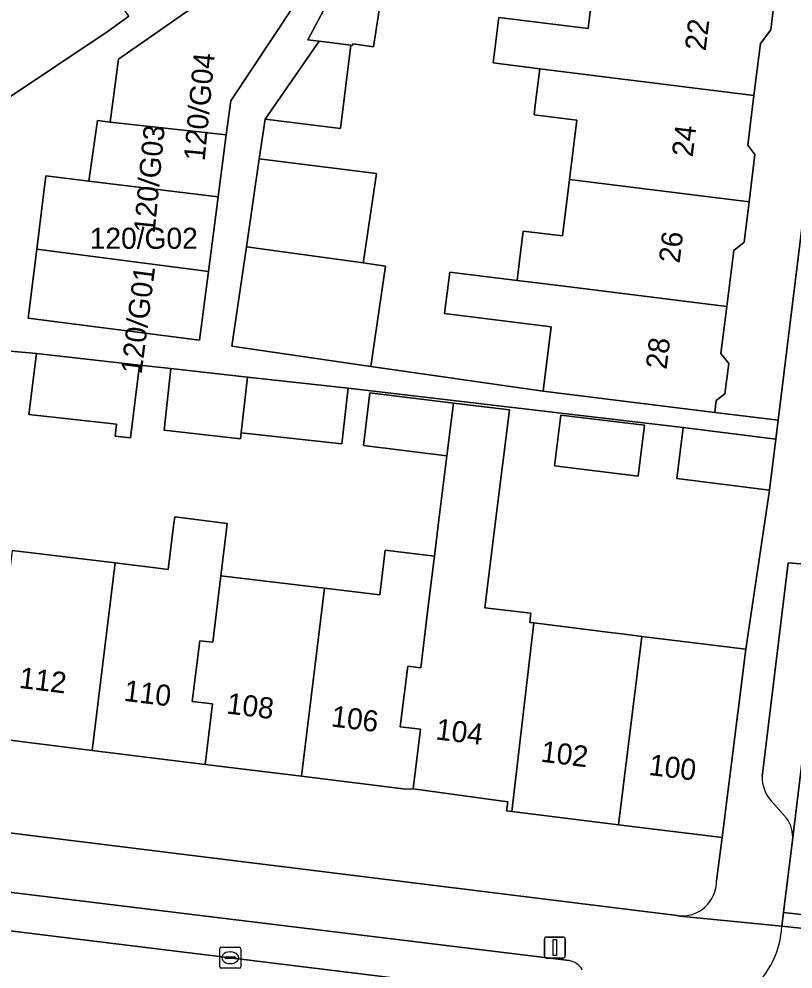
# Model space of a CAD drawing. Extents: x 158086 to 159499, y 382904 to 383981.
# Drawn here: x 158208.93 to 158245.67, y 383286 to 383331.09 of the extents above; entities that cross this region are included whole.
import ezdxf

# ---------------------------------------------------------------- set-up
doc = ezdxf.new("R2010")
doc.units = 0
for name, color, linetype in [('IMGEO_Erf', 7, 'Continuous'), ('IMGEO_Kolk', 7, 'Continuous'), ('IMGEO_Lichtmast', 7, 'Continuous'), ('IMGEO_Muur', 7, 'Continuous'), ('IMGEO_Pand', 7, 'Continuous'), ('IMGEO_Pand_nummerreeks', 7, 'Continuous'), ('IMGEO_Parkeervlak_open', 7, 'Continuous'), ('IMGEO_Rijbaan_lokaal_open', 7, 'Continuous'), ('IMGEO_Voetpad_open', 7, 'Continuous')]:
    doc.layers.add(name, color=color, linetype=linetype)

msp = doc.modelspace()

# ---------------------------------------------------------------- linework, layer by layer
at = {"layer": 'IMGEO_Erf'}
for points in [[(158208.245, 383327.218), (158213.164, 383330.52), (158214.145, 383331.232), (158211.565, 383335.002), (158211.969, 383335.279), (158213.527, 383336.345), (158215.489, 383337.688), (158217.964, 383334.072), (158221.444, 383336.596), (158219.026, 383340.05), (158221.516, 383341.793), (158226.433, 383345.235), (158227.791, 383343.295), (158229.777, 383346.725), (158229.616, 383346.945), (158220.677, 383360.064), (158217.541, 383357.927), (158220.353, 383353.836), (158222.314, 383350.973), (158222.133, 383350.849), (158222.008, 383351.03), (158217.367, 383347.854), (158212.597, 383344.59), (158207.828, 383341.326)], [(158244.848, 383332.474), (158244.614, 383330.581), (158244.127, 383329.936), (158243.821, 383327.463), (158243.529, 383325.098), (158243.866, 383324.666), (158243.587, 383322.411), (158243.351, 383320.497), (158242.857, 383320.112), (158242.527, 383317.443), (158242.251, 383315.216), (158242.62, 383314.743), (158242.442, 383313.3), (158242.029, 383312.978), (158241.96, 383312.42), (158244.969, 383312.049), (158248.754, 383342.754)], [(158226.417, 383334.071), (158225.755, 383329.77), (158224.779, 383329.913), (158224.768, 383329.839), (158224.678, 383329.85), (158224.188, 383325.889), (158220.615, 383326.331), (158220.339, 383324.451), (158225.898, 383323.758), (158225.286, 383319.593), (158225.274, 383319.512), (158226.329, 383319.357), (158225.631, 383314.6), (158233.817, 383313.428), (158234.195, 383316.488), (158229.132, 383317.114), (158229.377, 383319.083), (158232.578, 383318.684), (158232.695, 383319.619), (158232.87, 383321.027), (158234.728, 383320.796), (158235.059, 383323.474), (158235.407, 383326.289), (158233.386, 383326.539), (158233.435, 383327.001), (158233.651, 383328.731), (158231.447, 383329.005), (158231.714, 383331.169), (158235.946, 383330.645), (158236.304, 383333.54)], [(158244.558, 383308.736), (158240.162, 383309.282), (158240.462, 383311.698), (158224.555, 383313.567), (158224.261, 383310.922), (158219.479, 383311.454), (158219.448, 383311.171), (158215.817, 383311.575), (158216.142, 383314.503), (158214.649, 383314.669), (158214.226, 383311.213), (158213.501, 383311.294), (158213.564, 383311.862), (158209.401, 383312.325), (158209.755, 383315.214), (158208.52, 383315.331)], [(158208.611, 383305.869), (158213.499, 383305.277), (158215.542, 383305.029), (158216.018, 383304.971), (158216.272, 383307.044), (158216.323, 383307.459), (158218.819, 383307.154), (158218.768, 383306.738), (158218.515, 383304.669), (158223.441, 383304.072), (158226.063, 383303.755), (158226.32, 383305.874), (158228.647, 383305.592), (158228.86, 383307.328), (158229.239, 383310.366), (158225.285, 383310.845), (158225.588, 383313.346), (158229.551, 383312.866), (158232.209, 383312.542), (158231.519, 383307.003), (158231.048, 383303.151), (158233.231, 383302.886), (158233.176, 383302.449), (158233.37, 383302.425), (158237.125, 383301.959), (158237.544, 383301.907), (158238.492, 383301.789), (158243.427, 383301.176), (158244.558, 383308.736)], [(158242.045, 383290.194), (158242.318, 383292.241), (158237.395, 383292.848), (158232.321, 383293.474), (158232.077, 383293.504), (158232.131, 383293.941), (158227.639, 383294.56), (158227.294, 383294.539), (158222.349, 383295.15), (158217.761, 383295.716), (158212.41, 383296.378), (158207.86, 383296.94)], [(158186.591, 383295.165), (158240.182, 383288.537)]]:
    msp.add_lwpolyline(points, dxfattribs=at)
msp.add_lwpolyline([(158234.354, 383309.878), (158234.649, 383312.293), (158238.617, 383311.808), (158238.321, 383309.393)], close=True, dxfattribs=at)
msp.add_arc((158240.399, 383290.169), 1.647, 262.44, 0.8614, dxfattribs=at)
at = {"layer": 'IMGEO_Kolk'}
for p, q in [((158218.46, 383286.111), (158218.46, 383286.963)), ((158218.535, 383287.037), (158219.387, 383287.037)), ((158218.948, 383286.817), (158218.973, 383286.817)), ((158219.461, 383286.963), (158219.461, 383286.111)), ((158218.719, 383286.531), (158218.719, 383286.543)), ((158219.157, 383286.494), (158218.759, 383286.494)), ((158218.762, 383286.58), (158219.16, 383286.58)), ((158219.203, 383286.543), (158219.203, 383286.531)), ((158219.387, 383286.037), (158218.535, 383286.037)), ((158218.971, 383286.257), (158218.946, 383286.257))]:
    msp.add_line(p, q, dxfattribs=at)
for points in [[(158218.46, 383286.111), (158218.46, 383286.963)], [(158218.535, 383287.037), (158219.387, 383287.037)], [(158219.461, 383286.963), (158219.461, 383286.111)], [(158219.387, 383286.037), (158218.535, 383286.037)]]:
    msp.add_lwpolyline(points, dxfattribs=at)
for centre, radius, start, end in [((158218.537, 383286.961), 0.0765, 91.552, 178.448), ((158218.537, 383286.961), 0.0765, 91.552, 178.448), ((158219.385, 383286.961), 0.0765, 1.552, 88.448), ((158219.385, 383286.961), 0.0765, 1.552, 88.448), ((158218.759, 383286.54), 0.0403, 85.8775, 175.7526), ((158218.756, 383286.53), 0.0366, 178.938, 274.7102), ((158219.16, 383286.537), 0.043, 264.8664, 352.4533), ((158219.164, 383286.542), 0.0386, 1.7309, 96.639), ((158218.537, 383286.113), 0.0765, 181.552, 268.448), ((158218.537, 383286.113), 0.0765, 181.552, 268.448), ((158219.385, 383286.113), 0.0765, 271.552, 358.448), ((158219.385, 383286.113), 0.0765, 271.552, 358.448)]:
    msp.add_arc(centre, radius, start, end, dxfattribs=at)
for centre, major_axis, ratio, start_param, end_param in [((158218.947, 383286.537), (-0.387, 0.002), 0.722429, 4.712389, 7.853982), ((158218.972, 383286.537), (-0.39, 0.002), 0.717154, 1.570796, 4.712389)]:
    msp.add_ellipse(centre, major_axis=major_axis, ratio=ratio, start_param=start_param, end_param=end_param, dxfattribs=at)
at = {"layer": 'IMGEO_Lichtmast'}
for p, q in [((158233.87, 383286.621), (158233.87, 383287.421)), ((158233.87, 383287.421), (158233.87, 383286.621)), ((158233.97, 383287.521), (158234.76, 383287.521)), ((158234.76, 383287.521), (158233.97, 383287.521)), ((158234.86, 383287.421), (158234.86, 383286.621)), ((158234.86, 383286.621), (158234.86, 383287.421)), ((158234.76, 383286.521), (158233.97, 383286.521)), ((158233.97, 383286.521), (158234.76, 383286.521))]:
    msp.add_line(p, q, dxfattribs=at)
msp.add_lwpolyline([(158234.29, 383287.396), (158234.44, 383287.396), (158234.44, 383286.646), (158234.29, 383286.646), (158234.29, 383287.396)], dxfattribs=at)
for centre, start, end in [((158233.97, 383287.421), 90, 180), ((158233.97, 383287.421), 90, 180), ((158234.76, 383287.421), 0, 90), ((158234.76, 383287.421), 360, 90), ((158233.97, 383286.621), 180, 270), ((158233.97, 383286.621), 180, 270), ((158234.76, 383286.621), 270, 0), ((158234.76, 383286.621), 270, 0)]:
    msp.add_arc(centre, 0.1, start, end, dxfattribs=at)
at = {"layer": 'IMGEO_Muur'}
msp.add_lwpolyline([(158243.427, 383301.176), (158244.558, 383308.736)], dxfattribs=at)
at = {"layer": 'IMGEO_Pand'}
for points in [[(158213.263, 383326.202), (158218.772, 383325.599), (158218.982, 383327.205), (158223.006, 383333.289), (158221.37, 383334.581), (158213.649, 383329.189)], [(158226.417, 383334.071), (158225.321, 383334.187), (158224.849, 383334.237), (158222.636, 383330.105), (158223.174, 383330.038), (158224.678, 383329.85), (158224.768, 383329.839), (158224.779, 383329.913), (158225.755, 383329.77)], [(158244.848, 383332.474), (158236.304, 383333.54), (158235.946, 383330.645), (158231.714, 383331.169), (158231.447, 383329.005), (158233.651, 383328.731), (158235.678, 383328.478), (158243.821, 383327.463), (158244.127, 383329.936), (158244.614, 383330.581)], [(158224.678, 383329.85), (158223.174, 383330.038), (158220.615, 383326.331), (158224.188, 383325.889)], [(158243.821, 383327.463), (158235.678, 383328.478), (158233.651, 383328.731), (158233.435, 383327.001), (158233.386, 383326.539), (158235.407, 383326.289), (158235.059, 383323.474), (158243.587, 383322.411), (158243.866, 383324.666), (158243.529, 383325.098)], [(158218.388, 383322.65), (158218.772, 383325.599), (158213.263, 383326.202), (158212.651, 383326.269), (158212.244, 383323.397)], [(158225.898, 383323.758), (158220.339, 383324.451), (158219.727, 383320.286), (158225.274, 383319.512), (158225.286, 383319.593)], [(158218.388, 383322.65), (158212.244, 383323.397), (158210.204, 383323.645), (158209.773, 383320.166), (158217.925, 383319.102)], [(158243.587, 383322.411), (158235.059, 383323.474), (158234.728, 383320.796), (158232.87, 383321.027), (158232.695, 383319.619), (158232.578, 383318.684), (158234.438, 383318.452), (158242.527, 383317.443), (158242.857, 383320.112), (158243.351, 383320.497)], [(158209.773, 383320.166), (158209.368, 383316.891), (158217.501, 383315.854), (158217.925, 383319.102)], [(158225.274, 383319.512), (158219.727, 383320.286), (158219.034, 383315.569), (158225.631, 383314.6), (158226.329, 383319.357)], [(158242.527, 383317.443), (158234.438, 383318.452), (158232.578, 383318.684), (158229.377, 383319.083), (158229.132, 383317.114), (158234.195, 383316.488), (158233.817, 383313.428), (158236.998, 383313.034), (158241.96, 383312.42), (158242.029, 383312.978), (158242.442, 383313.3), (158242.62, 383314.743), (158242.251, 383315.216)], [(158209.401, 383312.325), (158213.564, 383311.862), (158213.501, 383311.294), (158214.226, 383311.213), (158214.649, 383314.669), (158209.755, 383315.214)], [(158219.773, 383314.1), (158216.142, 383314.503), (158215.817, 383311.575), (158219.448, 383311.171), (158219.479, 383311.454)], [(158224.555, 383313.567), (158219.773, 383314.1), (158219.479, 383311.454), (158224.261, 383310.922)], [(158229.551, 383312.866), (158225.588, 383313.346), (158225.285, 383310.845), (158229.239, 383310.366)], [(158233.37, 383302.425), (158233.176, 383302.449), (158233.231, 383302.886), (158231.048, 383303.151), (158231.519, 383307.003), (158232.209, 383312.542), (158229.551, 383312.866), (158229.239, 383310.366), (158228.86, 383307.328), (158228.647, 383305.592), (158228.388, 383303.473), (158228, 383300.301), (158227.383, 383300.376), (158227.03, 383297.496), (158227.984, 383297.38), (158227.639, 383294.56), (158232.131, 383293.941), (158232.077, 383293.504), (158232.321, 383293.474)], [(158238.617, 383311.808), (158234.649, 383312.293), (158234.354, 383309.878), (158238.321, 383309.393)], [(158244.858, 383311.152), (158240.462, 383311.698), (158240.162, 383309.282), (158244.558, 383308.736)], [(158218.515, 383304.669), (158218.768, 383306.738), (158218.819, 383307.154), (158216.323, 383307.459), (158216.272, 383307.044), (158216.018, 383304.971), (158215.542, 383305.029), (158213.499, 383305.277), (158212.41, 383296.378), (158217.761, 383295.716), (158218.112, 383298.589), (158217.158, 383298.705), (158217.511, 383301.585), (158218.128, 383301.51)], [(158213.499, 383305.277), (158208.611, 383305.869), (158208.226, 383302.722), (158207.609, 383302.797), (158207.256, 383299.917), (158208.21, 383299.801), (158207.86, 383296.94), (158212.41, 383296.378)], [(158228.647, 383305.592), (158226.32, 383305.874), (158226.063, 383303.755), (158223.441, 383304.072), (158222.349, 383295.15), (158227.294, 383294.539), (158227.639, 383294.56), (158227.984, 383297.38), (158227.03, 383297.496), (158227.383, 383300.376), (158228, 383300.301), (158228.388, 383303.473)], [(158223.441, 383304.072), (158218.515, 383304.669), (158218.128, 383301.51), (158217.511, 383301.585), (158217.158, 383298.705), (158218.112, 383298.589), (158217.761, 383295.716), (158222.349, 383295.15)], [(158238.492, 383301.789), (158237.544, 383301.907), (158237.125, 383301.959), (158233.37, 383302.425), (158232.321, 383293.474), (158237.395, 383292.848)], [(158237.395, 383292.848), (158242.318, 383292.241), (158243.427, 383301.176), (158238.492, 383301.789)]]:
    msp.add_lwpolyline(points, close=True, dxfattribs=at)
at = {"layer": 'IMGEO_Parkeervlak_open'}
for points in [[(158245.651, 383292.117), (158248.198, 383313.075)], [(158246.443, 383305.195), (158245.449, 383305.274), (158244.209, 383295.135)], [(158154.333, 383294.506), (158155.383, 383294.36), (158159.222, 383293.902), (158167.743, 383292.859), (158167.892, 383292.844), (158169.18, 383292.668), (158185.736, 383290.605), (158202.298, 383288.579), (158218.957, 383286.536), (158235.058, 383284.554), (158237.514, 383284.273)], [(158244.64, 383293.977), (158245.367, 383293.16)], [(158235.044, 383286.403), (158202.228, 383290.415)]]:
    msp.add_lwpolyline(points, dxfattribs=at)
for centre, radius, start, end in [((158245.875, 383295.096), 1.667, 178.6603, 222.1696), ((158244.141, 383292.266), 1.517, 354.3606, 36.1031), ((158234.866, 383285.47), 0.95, 31.7724, 79.226)]:
    msp.add_arc(centre, radius, start, end, dxfattribs=at)
at = {"layer": 'IMGEO_Rijbaan_lokaal_open'}
for points in [[(158251.304, 383312.596), (158252.719, 383324.263), (158253.526, 383330.865), (158253.584, 383331.362), (158250.566, 383331.749), (158250.288, 383329.438), (158249.628, 383324.862), (158248.198, 383313.075), (158245.651, 383292.117), (158245.229, 383288.69), (158248.331, 383288.334), (158249.411, 383297.038)], [(158248.331, 383288.334), (158245.229, 383288.69), (158245.147, 383288.036), (158248.252, 383287.697)]]:
    msp.add_lwpolyline(points, close=True, dxfattribs=at)
for points in [[(158153.621, 383291.07), (158155.987, 383290.794), (158172.462, 383288.752), (158188.491, 383286.753), (158205.961, 383284.626), (158223.898, 383282.41), (158240.187, 383280.392), (158240.512, 383283.921), (158237.514, 383284.273), (158235.058, 383284.554), (158218.957, 383286.536), (158202.298, 383288.579), (158185.736, 383290.605)], [(158248.252, 383287.697), (158245.147, 383288.036)]]:
    msp.add_lwpolyline(points, dxfattribs=at)
msp.add_arc((158240.777, 383288.291), 4.378, 266.5359, 356.6621, dxfattribs=at)
at = {"layer": 'IMGEO_Voetpad_open'}
for points in [[(158246.003, 383377.378), (158243.473, 383375.686), (158248.263, 383368.693), (158248.054, 383368.524), (158251.026, 383363.997), (158250.892, 383362.545), (158250.39, 383355.99), (158250.387, 383355.956), (158250.128, 383353.89), (158249.12, 383345.719), (158248.754, 383342.754), (158244.969, 383312.049), (158244.858, 383311.152), (158244.558, 383308.736), (158243.427, 383301.176), (158242.318, 383292.241), (158242.045, 383290.194)], [(158208.52, 383315.331), (158209.755, 383315.214), (158214.649, 383314.669), (158216.142, 383314.503), (158219.773, 383314.1), (158224.555, 383313.567), (158240.462, 383311.698), (158244.858, 383311.152), (158244.969, 383312.049), (158241.96, 383312.42), (158236.998, 383313.034), (158233.817, 383313.428), (158225.631, 383314.6), (158219.034, 383315.569), (158219.727, 383320.286), (158220.339, 383324.451), (158220.615, 383326.331), (158223.174, 383330.038), (158222.636, 383330.105), (158224.849, 383334.237)], [(158214.145, 383331.232), (158213.164, 383330.52), (158208.245, 383327.218)], [(158244.209, 383295.135), (158245.449, 383305.274), (158246.443, 383305.195)], [(158245.147, 383288.036), (158240.303, 383288.508), (158240.182, 383288.537), (158186.591, 383295.165)], [(158245.367, 383293.16), (158244.64, 383293.977)], [(158240.182, 383288.537), (158240.303, 383288.508), (158245.147, 383288.036), (158245.229, 383288.69), (158245.651, 383292.117)], [(158202.228, 383290.415), (158235.044, 383286.403)]]:
    msp.add_lwpolyline(points, dxfattribs=at)
msp.add_lwpolyline([(158210.204, 383323.645), (158212.244, 383323.397), (158212.651, 383326.269), (158213.263, 383326.202), (158213.649, 383329.189), (158221.37, 383334.581), (158223.006, 383333.289), (158218.982, 383327.205), (158218.772, 383325.599), (158218.388, 383322.65), (158217.925, 383319.102), (158217.501, 383315.854), (158209.368, 383316.891), (158209.773, 383320.166)], close=True, dxfattribs=at)
for centre, radius, start, end in [((158245.875, 383295.096), 1.667, 178.6603, 222.1696), ((158244.141, 383292.266), 1.517, 354.3606, 36.1031), ((158240.399, 383290.169), 1.647, 262.44, 0.8614), ((158240.777, 383288.291), 4.378, 266.5359, 356.6621), ((158234.866, 383285.47), 0.95, 31.7724, 79.226)]:
    msp.add_arc(centre, radius, start, end, dxfattribs=at)

# ---------------------------------------------------------------- texts
at = {"layer": 'IMGEO_Pand_nummerreeks'}
for s, rotation, p in [('22', 82.9987, (158241.525, 383329.549)), ('120/G04', 84.5398, (158217.743, 383324.326)), ('120/G03', 84.5398, (158215.37, 383320.897)), ('24', 82.9987, (158240.906, 383324.511)), ('26', 82.9987, (158240.286, 383319.469)), ('120/G01', 82.7602, (158214.749, 383314.204)), ('28', 82.9987, (158239.668, 383314.431)), ('112', 352.9583, (158208.901, 383299.35)), ('110', 352.9583, (158213.873, 383298.736)), ('108', 352.9583, (158218.75, 383298.133)), ('106', 352.9583, (158223.712, 383297.52)), ('104', 352.9583, (158228.678, 383296.906)), ('102', 352.9698, (158233.667, 383295.847)), ('100', 352.9693, (158238.793, 383295.215))]:
    msp.add_text(s, height=1, rotation=rotation, dxfattribs=at).set_placement(p)
msp.add_text('120/G02', height=1, dxfattribs=at).set_placement((158212.288, 383320.184))

doc.saveas('drawing.dxf')
